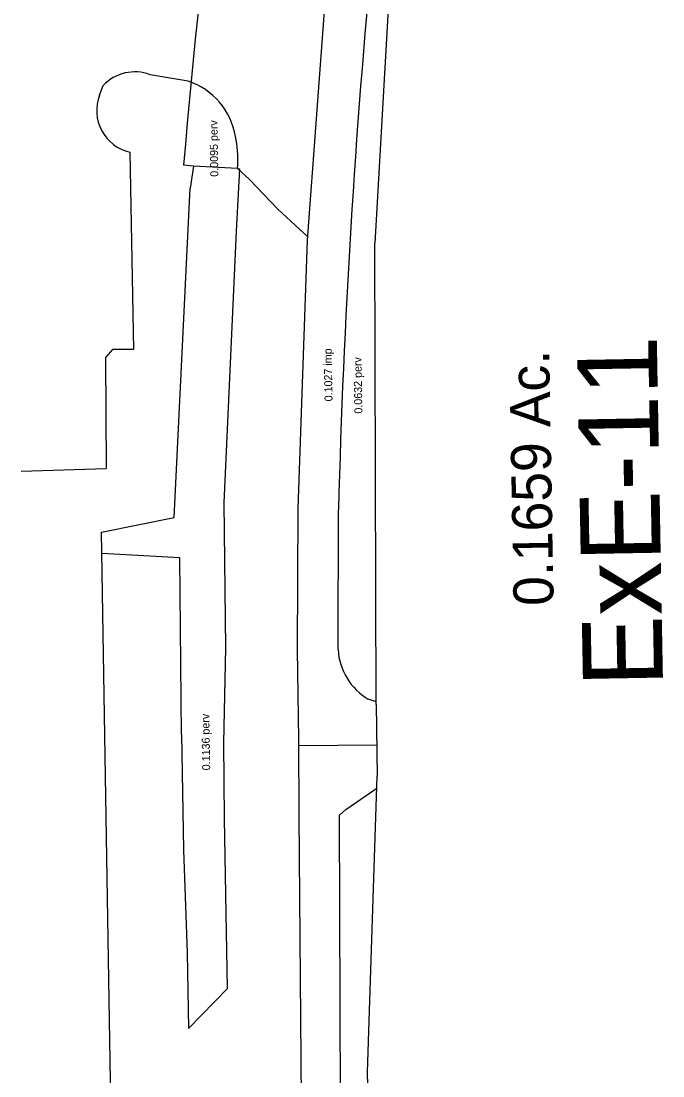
# Model space of a CAD drawing. Extents: x 925564 to 926134, y 853260 to 858402.
# Drawn here: x 925680.5 to 925905.1, y 857179 to 857548.1 of the extents above; entities that cross this region are included whole.
import ezdxf

# ---------------------------------------------------------------- set-up
doc = ezdxf.new("R2010")
doc.units = 0
for name, color, linetype in [('DrainDivides01', 7, 'Continuous'), ('PavtMisc_ep', 7, 'Continuous'), ('TextLabel', 7, 'Continuous')]:
    doc.layers.add(name, color=color, linetype=linetype)

msp = doc.modelspace()

# ---------------------------------------------------------------- linework, layer by layer
at = {"layer": 'DrainDivides01'}
for p, q in [((925813.91, 857637.85), (925804.32, 857470.39)), ((925780.72, 857471.45), (925788.69, 857577.98)), ((925740.82, 857497.31), (925737.37, 857497.6)), ((925777.48, 857377.55), (925780.72, 857471.45)), ((925804.72, 857308.93), (925804.32, 857470.39)), ((925777.27, 857328.03), (925777.48, 857377.55)), ((925777.66, 857296.72), (925777.27, 857328.03)), ((925804.72, 857308.93), (925805.15, 857283.93)), ((925777.87, 857269.9), (925777.66, 857296.72)), ((925804.96, 857294.73), (925777.68, 857294.52)), ((925801.78, 857180.29), (925805.15, 857283.93)), ((925778.72, 857160.03), (925777.87, 857269.9)), ((925809.63, 856710.62), (925801.78, 857180.29))]:
    msp.add_line(p, q, dxfattribs=at)
for points in [[(925756.28, 857496.43), (925740.82, 857497.31), (925739.67, 857489.56)], [(925756.28, 857496.43), (925760.47, 857492.64), (925770.37, 857482.28), (925780.99, 857472.5)], [(925708.61, 857369.25), (925734.12, 857374.33), (925739.67, 857489.56)], [(925724.71, 856410.17), (925734.71, 856410.34), (925730.14, 856679.29), (925729.65, 856708.82), (925726.87, 856874.9), (925716.87, 856874.74), (925713.51, 857076.08), (925713.01, 857106.07), (925708.61, 857369.25)]]:
    msp.add_lwpolyline(points, dxfattribs=at)
msp.add_arc((928061.19, 857302.51), 2332, 169.3984, 175.20115, dxfattribs=at)
at = {"layer": 'PavtMisc_ep'}
for p, q in [((925738.95, 857526.99), (925725.65, 857529.31)), ((925707.92, 857522.11), (925709.25, 857525.58)), ((925718.61, 857502.18), (925719.89, 857433.17)), ((925755.91, 857474.54), (925757.01, 857496.42)), ((925756.28, 857496.43), (925756.35, 857497.56)), ((925756.28, 857496.43), (925757.01, 857496.42)), ((925751.61, 857379.55), (925755.91, 857474.54)), ((925712.49, 857433.15), (925710, 857430.38)), ((925710, 857430.38), (925710.34, 857391.54)), ((925719.89, 857433.17), (925712.49, 857433.15)), ((925680.52, 857390.61), (925710.34, 857391.54)), ((925752.18, 857328.77), (925751.61, 857379.55)), ((925791.44, 857328.16), (925791.58, 857377.12)), ((925736.1, 857360.3), (925708.73, 857361.8)), ((925736.64, 857298.49), (925736.1, 857360.3)), ((925751.42, 857295.53), (925752.18, 857328.77)), ((925804.72, 857309.89), (925802, 857310.78)), ((925736.64, 857298.49), (925737.32, 857258.1)), ((925751.7, 857268.97), (925751.42, 857295.53)), ((925794.12, 857272.27), (925805.01, 857279.68)), ((925791.96, 857270.25), (925794.12, 857272.27)), ((925752.75, 857209.59), (925751.7, 857268.97)), ((925792.31, 857160.22), (925791.96, 857270.25)), ((925737.32, 857258.1), (925738.59, 857222.07)), ((925738.59, 857222.07), (925739.13, 857195.62)), ((925739.13, 857195.62), (925752.75, 857209.59))]:
    msp.add_line(p, q, dxfattribs=at)
for centre, major_axis, ratio, start_param, end_param in [((928603.71, 857303.24), (33.77, -2818.01), 0.998185, 4.604015, 4.674208), ((925720.27, 857515.09), (14.59, -4.29), 0.999214, 1.495209, 2.666784), ((925731.65, 857503.97), (-12.78, -20.48), 0.999303, 2.281287, 3.39284), ((925721.97, 857516.8), (-14.98, 1.02), 0.999063, 5.989587, 7.69645), ((925721.67, 857499.73), (-27.13, -21.71), 0.999496, 2.403807, 2.696306), ((925813.02, 857329.44), (3.99, -21.33), 0.996136, 4.586971, 5.562724)]:
    msp.add_ellipse(centre, major_axis=major_axis, ratio=ratio, start_param=start_param, end_param=end_param, dxfattribs=at)

# ---------------------------------------------------------------- texts
at = {"layer": 'TextLabel'}
for s, height, p in [('0.0095 perv', 2.8, (925749.56, 857493.63)), ('ExE-11', 28, (925905.17, 857315.32)), ('0.1027 imp', 2.8, (925789.52, 857415.04)), ('0.0632 perv', 2.8, (925799.96, 857410.75)), ('0.1659 Ac.', 14, (925866.89, 857343.58)), ('0.1136 perv', 2.8, (925746.72, 857285.96))]:
    msp.add_text(s, height=height, rotation=91.0261, dxfattribs=at).set_placement(p)

doc.saveas('drawing.dxf')
